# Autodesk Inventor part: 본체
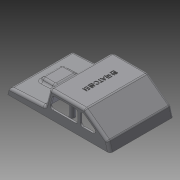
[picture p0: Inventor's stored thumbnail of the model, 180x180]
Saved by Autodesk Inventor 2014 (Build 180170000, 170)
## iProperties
Created: 2015-06
Part Number: 본체
Material: Generic
Document SubType Name: Modeling
Designer: Administrator
Density: 1 g/cm^3
Appearance: Default
Author: Administrator
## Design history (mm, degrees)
sketch "스케치7"
  geometry: L1 (61, 0)-(-61, 0); L2 (61, 0)-(58.856, 8); L3 (58.856, 8)-(47.856, 8.576); L4 (47.856, 8.576)-(46.504, 13); L5 (46.504, 13)-(29.289, 13); L6 (27.856, 9.625)-(16.856, 10.201); L7 (16.856, 10.201)-(11.283, 31); L8 (11.283, 31)-(-31, 31); L9 (-31, 31)-(-58.053, 11); L10 (-58.053, 11)-(-61, 0); L11 (-61, 0)-(-61, 11); L12 (-61, 11)-(-58.053, 11); L13 (61, 0)-(61, 8); L14 (61, 8)-(58.856, 8); L15 (29.289, 13)-(27.856, 9.625); L16 (52.667, 0)-(52.667, -1); L17 (52.667, -1)-(-60, -1); L18 (-60, -1)-(-60, 0); 2 further points
  constraints: 36 end point, 7 perpendicular, 3 parallel, 2 collinear, 2 point on line, 1 coincident, 1 horizontal, 1 midpoint
  dimensions: "d12" = 122 distance of L1.start L1.end; "d13" = 31 vertical distance of L8.end L1.end; "d14" = 30 horizontal distance of L11.end L8.end; "d15" = 20 vertical distance of L9.end L8.end; "d16" = 8 vertical distance of L2.end L1.start; "d17" = 42 horizontal distance of L6.end L2.end; "d18" = 11 horizontal distance of L3.end L2.end; "d19" = 105 deg angle of L1 L2; "d20" = 105 deg angle of L1 L10; "d22" = 20 horizontal distance of L6.start L3.end; "d23" = 3 deg angle of L1 L6; "d24" = 70 deg angle of L3 L4; "d25" = 70 deg angle of L6 L15; "d26" = 5 vertical distance of L4.end L2.end; "d62" = 1 horizontal distance of L1.end L17.end; "d63" = 1 distance between parallel lines of L1 L17
extrude "돌출3" new body sketch "스케치7" stored distance "d27" = 76; taper "d28" = 0 deg
sketch "스케치8"
  geometry: L1 (-27.856, 9.625)-(-29.289, 13) reference; L2 (-29.289, 13)-(-46.504, 13) reference; L3 (-46.504, 13)-(-47.856, 8.576) reference; L4 (-47.856, 8.576)-(-58.856, 8) reference; L5 (-47.856, 8.576)-(-27.856, 9.625); 1 further point
  constraints: 2 end point, 1 collinear
extrude "돌출4" cut sketch "스케치8" distance "d29" = 25; taper "d30" = 0 deg
sketch "스케치9"
  geometry: L1 (-47.856, -8.576)-(-46.504, -13) reference; L2 (-46.504, -13)-(-29.289, -13) reference; L3 (-29.289, -13)-(-27.856, -9.625) reference; L4 (-27.856, -9.625)-(-16.856, -10.201) reference; L5 (-47.856, -8.576)-(-27.856, -9.625); 1 further point
  constraints: 2 end point, 1 collinear
extrude "돌출5" cut sketch "스케치9" distance "d31" = 25; taper "d32" = 0 deg
feature "쉘1" dims "d33" = 2
sketch "스케치10"
  geometry: L1 (31, 31)-(-11.283, 31) reference; L2 (-11.283, 31)-(-16.856, 10.201) reference; L3 (-5.145, 26)-(19.534, 26); L4 (22.534, 23)-(22.534, 14); L5 (19.534, 11)-(-7.556, 11); L6 (-10.454, 14.776)-(-8.043, 23.776); A1 r 3 centre (-5.145, 23) between (-5.145, 26) and (-8.043, 23.776); A2 r 3 centre (-7.556, 14) between (-10.454, 14.776) and (-7.556, 11); A3 r 3 centre (19.534, 14) between (19.534, 11) and (22.534, 14); A4 r 3 centre (19.534, 23) between (22.534, 23) and (19.534, 26); 3 further points
  constraints: 8 end point, 8 point on circle, 8 tangent, 4 centre point, 4 point on line, 3 equal radius, 3 parallel, 1 perpendicular
  dimensions: "d34" = 5 distance between parallel lines of L6 L2; "d35" = 34 distance of point (22.534, 11) point (-11.466, 11); "d36" = 5 distance between parallel lines of L1 L3; "d37" = 15 distance between parallel lines of L5 L3; "d38" = 3 radius of A1
extrude "돌출6" cut sketch "스케치10" stored distance "d39" = 25; taper "d40" = 0 deg
sketch "스케치11"
  geometry: L1 (58.053, 11)-(31, 31) reference; L2 (31, 31)-(-11.283, 31) reference; L3 (25.364, 23)-(25.364, 14); L4 (28.364, 11)-(40.538, 11); L5 (42.321, 16.412)-(30.147, 25.412); A1 r 3 centre (19.534, 23) between (22.534, 23) and (19.534, 26) reference; A2 r 3 centre (19.534, 14) between (19.534, 11) and (22.534, 14) reference; A3 r 3 centre (28.364, 23) between (30.147, 25.412) and (25.364, 23); A4 r 3 centre (28.364, 14) between (25.364, 14) and (28.364, 11); A5 r 3 centre (40.538, 14) between (40.538, 11) and (42.321, 16.412); 1 further point
  constraints: 6 end point, 6 point on circle, 6 tangent, 3 centre point, 2 horizontal alignment, 2 perpendicular, 1 parallel
  dimensions: "d41" = 5 distance between parallel lines of L1 L5; "d42" = 3 radius of A3; "d43" = 3 radius of A4; "d44" = 3 radius of A5
extrude "돌출7" cut sketch "스케치11" stored distance "d45" = 25; taper "d46" = 0 deg
sketch "스케치12"
  geometry: A1 r 4 centre (-8.282, 59) between (-8.282, 55) and (-8.282, 63); A2 r 4 centre (-8.282, 48) between (-8.282, 44) and (-8.282, 52); A3 r 4 centre (-8.282, 28) between (-8.282, 24) and (-8.282, 32); A4 r 4 centre (-8.282, 17) between (-8.282, 13) and (-8.282, 21); 3 further points
  constraints: 8 point on circle, 4 centre point, 13 other
  dimensions: "d47" = 8 diameter of A1; "d48" = 8 diameter of A2; "d49" = 8 diameter of A3; "d50" = 8 diameter of A4; "d51" = 10 vertical distance of A2.centre point (7.506, 38); "d52" = 10 vertical distance of A3.centre point (7.506, 38); "d53" = 11 distance of A4.centre A3.centre; "d54" = 11 distance of A1.centre A2.centre
extrude "돌출8" join sketch "스케치12" distance "d55" = 2; taper "d56" = 0 deg
fillet "모깎기3" dims "d57" = 3
fillet "모깎기4" dims "d58" = 3
fillet "모깎기5" dims "d59" = 3
fillet "모깎기6" dims "d60" = 3
fillet "모깎기7" dims "d61" = 3
sketch "스케치15"
  geometry: L1 (-61, -38)-(57.894, -38) reference; L2 (-61, -38)-(-61, -25) reference; L3 (-58.929, 36)-(-58.929, -36) reference; L4 (56.302, 36)-(56.302, -36) reference; L5 (58.929, 36)-(-58.929, 36) reference; L6 (-58.929, -36)-(58.929, -36) reference; C1 r 3 at (-40, 0); C2 r 3 at (0, 22); C3 r 3 at (40, 0); C4 r 3 at (0, -22); 1 further point
  constraints: 4 centre point, 2 horizontal alignment, 2 vertical alignment
  dimensions: "d65" = 6 diameter of C1; "d66" = 6 diameter of C2; "d67" = 6 diameter of C3; "d68" = 6 diameter of C4; "d69" = 40 distance of C1.centre point (0, 0); "d70" = 40 distance of C3.centre point (0, 0); "d71" = 22 distance of C2.centre point (0, 0); "d72" = 22 distance of C4.centre point (0, 0)
extrude "돌출9" join sketch "스케치15" stored distance "d73" = 2; taper "d74" = 0 deg
sketch "스케치16"
  geometry: L1 (69.981, 0)-(69.981, -70) reference; 2 further points
  constraints: 1 horizontal alignment, 1 other
  dimensions: "d75" = 50 distance from line of L1 point (19.981, -35)
feature "엠보싱1" sketch "스케치16" dims "d76" = 0.5, "d77" = 0
fillet "모깎기8" dims "d97" = 3
fillet "모깎기9" dims "d98" = 3
fillet "모깎기10" dims "d99" = 3
fillet "모깎기11" dims "d100" = 3
node "솔리드2"
